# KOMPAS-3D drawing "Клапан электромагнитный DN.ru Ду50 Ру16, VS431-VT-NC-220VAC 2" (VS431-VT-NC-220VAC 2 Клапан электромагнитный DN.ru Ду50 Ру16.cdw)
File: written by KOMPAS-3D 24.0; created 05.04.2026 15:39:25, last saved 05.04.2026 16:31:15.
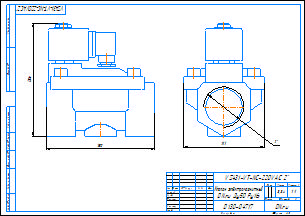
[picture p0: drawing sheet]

Document properties: c3d_UniqueCompID: ef56311e-7521-43dc-8291-0e6108b3d81d; Автор: artio; Класс точности: c; Знак неуказанной шероховатости: Шероховатость не задана; Рассекать на разрезах: Да; c3d_UniqueCompID: ef56311e-7521-43dc-8291-0e6108b3d81d; Автор: artio; Класс точности: c; Знак неуказанной шероховатости: Шероховатость не задана; Рассекать на разрезах: Да; c3d_UniqueCompID: ef56311e-7521-43dc-8291-0e6108b3d81d; Автор: artio; Класс точности: c; Знак неуказанной шероховатости: Шероховатость не задана; Рассекать на разрезах: Да; c3d_UniqueCompID: ef56311e-7521-43dc-8291-0e6108b3d81d; Автор: artio; Класс точности: c; Знак неуказанной шероховатости: Шероховатость не задана; Рассекать на разрезах: Да; c3d_UniqueCompID: ef56311e-7521-43dc-8291-0e6108b3d81d; Автор: artio; Класс точности: c; Знак неуказанной шероховатости: Шероховатость не задана; Рассекать на разрезах: Да; Автор: artio; Форматы листов документа: A3; Полное имя файла: VS431-VT-NC-220VAC 2 Клапан электромагнитный DN.ru Ду50 Ру16.m3d; Масса: 3.341; Наименование: Клапан электромагнитный DN.ru Ду50 Ру16; Количество листов документа: 1; Примечание: D130-04717

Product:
- Body: Тело 1  | qty 1
    Масса: 6.703651
- Part/product: Клапан электромагнитный DN.ru Ду50 Ру16  | designation VS431-VT-NC-220VAC 2
    Масса: 3.341
    Раздел спецификации: Прочие изделия
    Примечание: D130-04717
    additional columns: ef56311e-7521-43dc-8291-0e6108b3d81d; artio; c; Шероховатость не задана; Да

Views: Вид 1, Спереди
Referenced files in C:\Users\artio\OneDrive\Рабочий стол\Клапан электромагнитный DN.ru\VS431\VS431-ET-NC\: VS431-ET-NC-220VAC 3-4 Клапан электромагнитный DN.ru Ду20 Ру16.m3d, VS431-ET-NC-220VAC 3-4 Клапан электромагнитный DN.ru Ду20 Ру16.cdw
Referenced files in C:\Users\artio\OneDrive\Рабочий стол\Клапан электромагнитный DN.ru\VS431\VS431-VT-NC\: VS431-VT-NC-220VAC 2 Клапан электромагнитный DN.ru Ду50 Ру16.m3d
Referenced files in C:\Users\artio\OneDrive\Рабочий стол\Клапан электромагнитный DN.ru\VS431\VS431-VT-NC\VS431-VT-NC-220VAC\Ду50\: VS431-VT-NC-220VAC 2 Клапан электромагнитный DN.ru Ду50 Ру16.m3d
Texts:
  VS431-VT-NC-220VAC 2
  Клапан электромагнитный
  DN.ru Ду50 Ру16
  VS431-VT-NC-220VAC 2"
  VS431-VT-NC-220VAC 2"-
  Клапан электромагнитный DN.ru Ду50 Ру16
  VS431-VT-NC-220VAC 2 Клапан электромагнитный DN.ru Ду50 Ру16
Dimensions and other numbers on the sheet: 0; 3; 2; 4; 111; 1:1; 1; 3,34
